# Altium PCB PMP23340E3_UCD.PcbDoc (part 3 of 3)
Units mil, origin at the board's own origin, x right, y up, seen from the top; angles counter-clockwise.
Board outline 2299.21 x 1157.48 mil, 14 copper layers (Top Layer, Layer 1, Layer 2, Layer 3, Layer 4, Layer 5, Layer 6, Layer 7, Layer 8, Layer 9, Layer 10, Layer 11, Layer 12, Bottom Layer), stack 130 mil thick; 242 components, 71 nets, 1021 pads, 321 vias.
Unrouted connection lines stored in the file: 1.
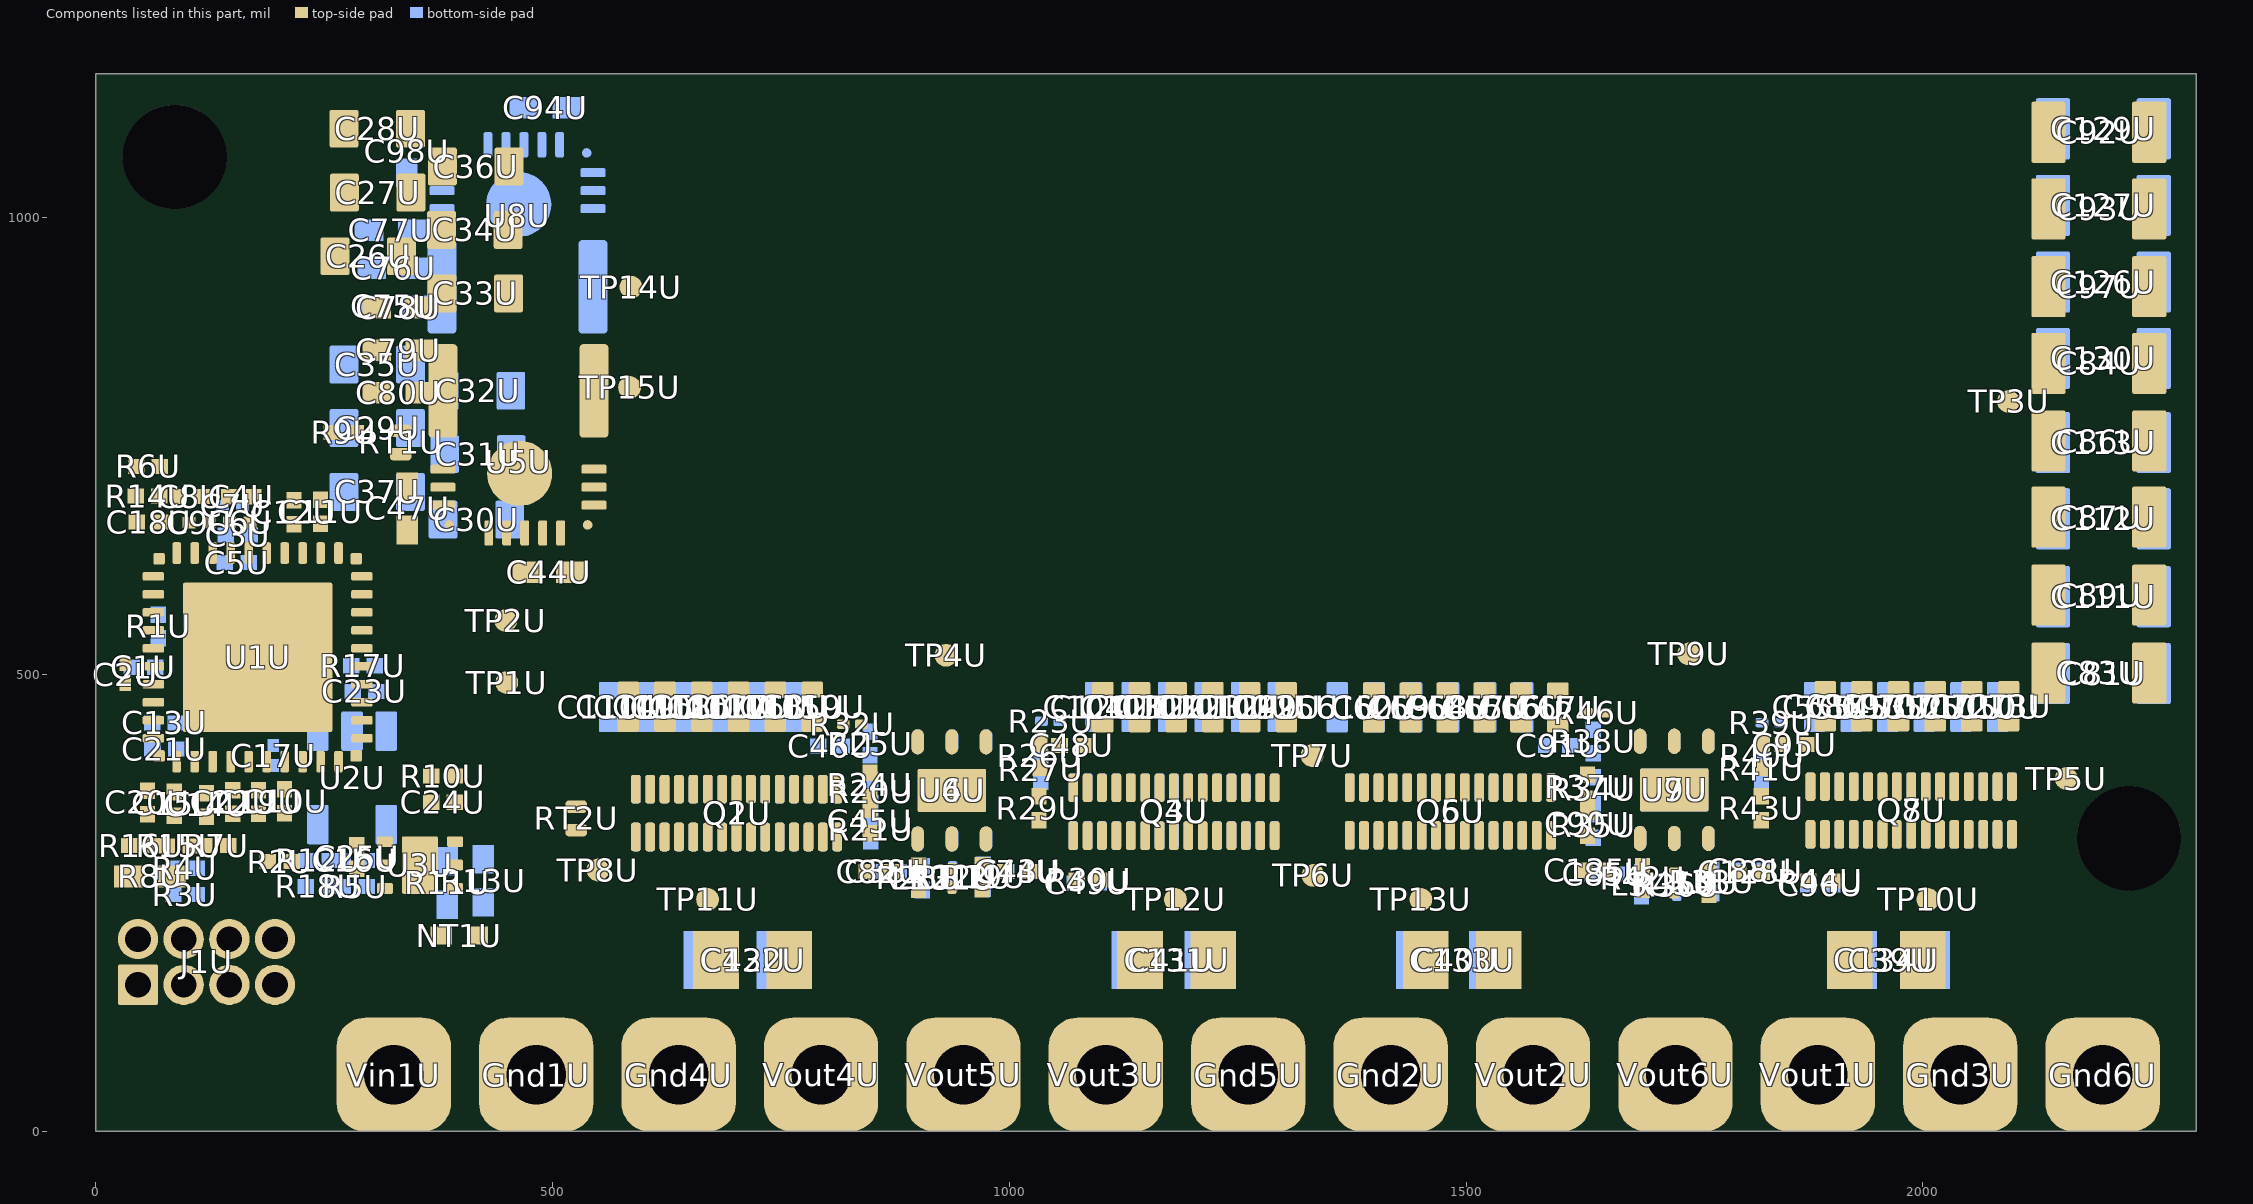
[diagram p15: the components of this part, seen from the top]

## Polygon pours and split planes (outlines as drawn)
3_3V_D on Layer 2 "LAYER_2_3_3V_D_P1355" (solid, pour order 1355): 18.43,785.67 307.08,785.67 307.08,641.01 307.08,240.65 17.11,240.65
Vsw2 on Layer 2 "LAYER_2_VSW2_P1378" (solid, remove dead copper, pour order 1378): 560.6,976.49 514.62,976.49 514.62,873.03 560.21,873.03
Vin on Layer 2 "LAYER_2_VIN_P1347" (solid, remove dead copper, pour order 1347): 258.75,-0.36 258.75,190.9 285.93,218.07 285.93,988.08 410.25,988.08 410.25,-0.36
Vsw2 on Layer 2 "LAYER_2_VSW2_P1360" (solid, pour order 1360): 1019,702.35 1102.45,702.35 1452.37,1052.26 1452.37,1157.48 1336.59,1157.48 1336.59,1041.7 1091.16,796.27 1019,796.27
Vsw2 on Layer 2 "LAYER_2_VSW2_P1359" (solid, pour order 1359): 1623.34,913.48 1544.79,913.48 1224.94,593.63 1224.94,464.14 1337.82,464.14 1337.82,615.42 1537.09,814.69 1623.34,814.69
Vsw2 on Layer 2 "LAYER_2_VSW2_P1358" (solid, pour order 1358): 825.77,813.5 825.77,772.44 745.11,772.44 587.65,929.9 587.65,1146.8 1327.7,1146.8 1327.7,1036.14 1105.05,813.5
Vsw2 on Layer 2 "LAYER_2_VSW2_P1357" (solid, pour order 1357): 1348.12,464.14 1348.12,609.51 1540.36,801.74 2184.87,801.74 2184.87,1132.49 2318.9,1132.49 2318.9,464.14
Vsw1 on Layer 2 "LAYER_2_VSW1_P1356" (solid, pour order 1356): 516.37,887.47 614.07,887.47 688.83,812.72 737.92,763.62 840.05,763.62 887.62,701.45 1109.66,701.45 1462.51,1054.3 1462.51,1157.48 2204.77,1157.48 2204.77,1103.27 2204.77,1054.3 2204.77,1012.9 2204.77,964.9 2204.77,929.81 2204.77,881.3 2204.77,843.85 2204.77,812.72 1762.75,812.72 1762.75,913.66 1531.32,913.66 1213.12,598 1213.12,464.73 516.37,464.73
GND on Layer 2 "LAYER_2_GND_P1337" (solid, remove dead copper, pour order 1337): 406.75,999.52 287.75,999.52 287.75,801.68 200.84,801.68 200.84,1142.83 516.38,1142.83 516.38,457.97 2299.21,457.97 2299.21,0 406.75,0
GND on Layer 1 "LAYER_1_GND_P1257" (solid, remove dead copper, pour order 1257): 409.05,393.09 409.05,651.79 267.66,793.18 20.22,793.18 20.22,1157.48 813.4,1157.48 813.4,0 409.05,0
AGND on Layer 1 "LAYER_1_AGND_P1366" (solid, remove dead copper, pour order 1366): -2.08,774.32 271.03,774.32 401.15,644.2 401.15,180.82 -0.49,183.79
Vin on Layer 1 "LAYER_1_VIN_P1409" (solid, remove dead copper, pour order 1409): 396.59,978.3 350.61,978.3 350.61,874.85 396.19,874.85
Vin on Layer 1 "LAYER_1_VIN_P1408" (solid, remove dead copper, pour order 1408): 396.58,862.96 350.61,862.96 350.61,758.81 396.58,758.81
Vsw2 on Layer 1 "LAYER_1_VSW2_P1388" (solid, remove dead copper, pour order 1388): 560.6,976.49 514.62,976.49 514.62,873.03 560.21,873.03
Vsw1 on Layer 1 "LAYER_1_VSW1_P1387" (solid, remove dead copper, pour order 1387): 560.6,861.14 514.62,861.14 514.62,757 560.6,757
Vout on Layer 1 "LAYER_1_VOUT_P1253" (solid, pour order 1253): 556.45,1159.56 1332.47,1159.56 1332.47,312.76 1055.48,312.76 1055.48,783.06 1048.79,783.06 1048.79,225.84 1169.05,105.58 1169.05,24.53 732.85,24.53 732.85,118.18 819.58,204.9 819.58,469.4 556.45,469.4
Vout on Layer 1 "LAYER_1_VOUT_P1254" (solid, pour order 1254): 2126.38,1159.56 1343.19,1159.56 1343.19,312.76 1627.35,312.76 1627.35,783.06 1634.04,783.06 1634.04,225.84 1513.78,105.58 1513.78,24.53 1949.98,24.53 1949.98,118.18 1863.25,204.9 1863.25,469.4 2126.38,469.4
GND on Layer 1 "LAYER_1_GND_P1259" (solid, remove dead copper, pour order 1259): 1042.74,446.09 1623.19,446.09 1623.19,0 1042.74,0
GND on Layer 1 "LAYER_1_GND_P1258" (solid, remove dead copper, pour order 1258): 1780.53,458.19 2299.21,458.19 2299.21,0 1780.53,0
Vsw2 on Layer 1 "LAYER_1_VSW2_P1256" (solid, remove dead copper, pour order 1256): 2180.71,1134.88 2299.21,1134.88 2299.21,468.21 2180.71,471.21
Vsw1 on Layer 1 "LAYER_1_VSW1_P1255" (solid, remove dead copper, pour order 1255): 2117.33,1129.97 2200.92,1129.97 2200.92,464.18 2117.33,466.29
Vsw1 on Layer 5 "LAYER_5_VSW1_P1385" (solid, remove dead copper, pour order 1385): 560.6,861.14 514.62,861.14 514.62,757 560.6,757
Vsw2 on Layer 5 "LAYER_5_VSW2_P1364" (solid, pour order 1364): 1636.57,713.56 1544.04,713.56 1238.17,1019.43 1238.17,1135.02 1350.46,1135.02 1350.46,1012.21 1562.32,800.35 1636.57,800.35
Vsw2 on Layer 5 "LAYER_5_VSW2_P1363" (solid, pour order 1363): 1054.5,897.77 1120.23,897.77 1439.92,578.08 1439.92,463.99 1327.98,463.99 1327.98,583.24 1101.83,809.38 1054.5,809.38
Vsw2 on Layer 5 "LAYER_5_VSW2_P1362" (solid, pour order 1362): 774.15,972.53 901.93,972.53 968.13,906.34 1126.73,906.34 1448.64,584.42 1448.64,463.61 2153.57,463.61 2153.57,1157.48 1359.29,1157.48 1359.29,1019.99 1564.59,814.69 1754.33,814.69 1754.33,703.2 1543.45,703.2 1230.33,1016.32 1230.33,1157.48 513.74,1157.48 513.74,878.54 680.16,878.54
Vsw2 on Layer 5 "LAYER_5_VSW2_P1361" (solid, pour order 1361): 775.5,960.07 901.14,960.07 ccw(c909.35,963.8) 902.97,957.43 1061.31,799.08 1108.02,799.08 1318.92,588.19 1318.92,464.37 558.32,464.37 558.32,875.88 691.31,875.88
Vin on Layer 5 "LAYER_5_VIN_P1352" (solid, remove dead copper, pour order 1352): 258.75,-0.36 258.75,190.9 285.93,218.07 285.93,976.65 410.25,976.65 410.25,-0.36
GND on Layer 5 "LAYER_5_GND_P1338" (solid, remove dead copper, pour order 1338): 414.88,980.66 284.75,980.66 284.75,799.39 234,799.39 234,1157.48 514.84,1157.48 514.84,745.48 553.1,745.48 553.1,452.31 2299.21,452.31 2299.21,0 414.88,0
Vsw2 on Layer 5 "LAYER_5_VSW2_P1282" (solid, remove dead copper, pour order 1282): 2180.71,1134.88 2299.21,1134.88 2299.21,468.21 2180.71,471.21
Vsw1 on Layer 5 "LAYER_5_VSW1_P1279" (solid, remove dead copper, pour order 1279): 2117.33,1129.97 2200.92,1129.97 2200.92,464.18 2117.33,466.29
Vsw2 on Layer 8 "LAYER_8_VSW2_P1386" (solid, remove dead copper, pour order 1386): 560.6,976.49 514.62,976.49 514.62,873.03 560.21,873.03
Vsw2 on Layer 8 "LAYER_8_VSW2_P1270" (solid, pour order 1270): 825.77,813.5 825.77,772.44 745.11,772.44 587.65,929.9 587.65,1146.8 1327.7,1146.8 1327.7,1036.14 1105.05,813.5
Vsw2 on Layer 8 "LAYER_8_VSW2_P1269" (solid, pour order 1269): 1348.12,464.14 1348.12,609.51 1540.36,801.74 2184.87,801.74 2184.87,1132.49 2318.9,1132.49 2318.9,464.14
Vsw2 on Layer 8 "LAYER_8_VSW2_P1271" (solid, pour order 1271): 1623.34,913.48 1544.79,913.48 1224.94,593.63 1224.94,464.14 1337.82,464.14 1337.82,615.42 1537.09,814.69 1623.34,814.69
Vsw1 on Layer 8 "LAYER_8_VSW1_P1268" (solid, pour order 1268): 516.37,887.47 614.07,887.47 688.83,812.72 737.92,763.62 840.05,763.62 887.62,701.45 1109.66,701.45 1462.51,1054.3 1462.51,1157.48 2204.77,1157.48 2204.77,1103.27 2204.77,1054.3 2204.77,1012.9 2204.77,964.9 2204.77,929.81 2204.77,881.3 2204.77,843.85 2204.77,812.72 1762.75,812.72 1762.75,913.66 1531.32,913.66 1213.12,598 1213.12,464.73 516.37,464.73
Vsw2 on Layer 8 "LAYER_8_VSW2_P1272" (solid, pour order 1272): 1019,702.35 1102.45,702.35 1452.37,1052.26 1452.37,1157.48 1336.59,1157.48 1336.59,1041.7 1091.16,796.27 1019,796.27
GND on Layer 8 "LAYER_8_GND_P1293" (solid, remove dead copper, pour order 1293): 405.41,647.24 253.13,744.64 253.13,1157.48 512.5,1157.48 512.5,453.78 2299.21,453.78 2299.21,0 405.41,0
Vsw2 on Top Layer "TOP_LAYER_VSW2_P1384" (solid, remove dead copper, pour order 1384): 560.6,976.49 514.62,976.49 514.62,873.03 560.21,873.03
Vsw1 on Top Layer "TOP_LAYER_VSW1_P1383" (solid, remove dead copper, pour order 1383): 560.6,861.14 514.62,861.14 514.62,757 560.6,757
AGND on Top Layer "TOP_LAYER_AGND_P1275" (solid, remove dead copper, pour order 1275): 266.64,302.42 266.64,188.92 377.87,188.92 377.87,372.47 332.48,372.47 332.48,302.42 266.82,302.57
AGND on Top Layer "TOP_LAYER_AGND_P1292" (solid, remove dead copper, pour order 1292): 48.39,303.15 48.39,358.77 217.26,358.77 217.26,331.76 105.07,331.76 89.73,316.42 89.73,303.15
GND on Top Layer "TOP_LAYER_GND_P1291" (solid, remove dead copper, pour order 1291): 327.66,1129.9 327.66,872.01 327.66,792.25 201.19,792.25 201.19,1129.9
3_3V_D on Top Layer "TOP_LAYER_3_3V_D_P1276" (solid, remove dead copper, pour order 1276): 276.99,371.06 325.14,419.2 413.74,419.2 413.74,383.76 413.74,337.84 389.58,313.68 371.86,313.68 371.86,308.84 366.22,303.21 361.38,308.04 276.09,308.04
AGND on Top Layer "TOP_LAYER_AGND_P1289" (solid, remove dead copper, pour order 1289): 56.78,707.06 56.78,635.02 72.09,619.71 114.26,619.71 114.26,671.67 102.71,683.22 102.71,707.06
AGND on Top Layer "TOP_LAYER_AGND_P1288" (solid, remove dead copper, pour order 1288): 160.94,649.89 160.94,737.96 274.23,737.96 317.12,695.06 317.12,580.96 273.8,580.96 273.8,649.22
GND on Top Layer "TOP_LAYER_GND_P1286" (solid, remove dead copper, pour order 1286): 420.62,1076.69 520.04,1076.69 520.04,680.23 420.62,680.23
Vin on Top Layer "TOP_LAYER_VIN_P1285" (solid, remove dead copper, pour order 1285): 331.09,1134.47 419.78,1134.47 419.78,737.89 359.66,737.89 359.66,800.51 331.09,800.51
GND on Top Layer "TOP_LAYER_GND_P1280" (solid, remove dead copper, pour order 1280): 416.39,455.12 2299.21,455.12 2299.21,0 416.39,0
Vout on Top Layer "TOP_LAYER_VOUT_P1283" (solid, pour order 1283): 560.55,1147.1 922.24,1147.1 922.24,936.49 935.03,936.49 935.03,1147.1 1332.5,1147.1 1332.5,464.44 560.55,464.44
Vout on Top Layer "TOP_LAYER_VOUT_P1281" (solid, pour order 1281): 1343.19,1157.48 1722.4,1157.48 1722.4,923.28 1736.57,923.28 1736.57,1157.48 2131.72,1157.48 2131.72,464.86 1343.19,464.86
Vsw2 on Top Layer "TOP_LAYER_VSW2_P1278" (solid, remove dead copper, pour order 1278): 2180.71,1134.88 2299.21,1134.88 2299.21,468.21 2180.71,471.21
Vsw1 on Top Layer "TOP_LAYER_VSW1_P1277" (solid, remove dead copper, pour order 1277): 2117.33,1129.97 2200.92,1129.97 2200.92,464.18 2117.33,466.29
Vsw2 on Layer 7 "LAYER_7_VSW2_P1400" (solid, remove dead copper, pour order 1400): 560.6,976.49 514.62,976.49 514.62,873.03 560.21,873.03
Vsw1 on Layer 7 "LAYER_7_VSW1_P1399" (solid, remove dead copper, pour order 1399): 560.6,861.14 514.62,861.14 514.62,757 560.6,757
AGND on Layer 7 "LAYER_7_AGND_P1365" (solid, remove dead copper, pour order 1365): 17.53,778.15 302.54,778.15 302.54,245.07 20.5,245.07
Vout on Layer 7 "LAYER_7_VOUT_P1252" (solid, pour order 1252): 556.45,1159.56 1332.47,1159.56 1332.47,312.76 1055.48,312.76 1055.48,783.06 1048.79,783.06 1048.79,225.84 1169.05,105.58 1169.05,24.53 732.85,24.53 732.85,118.18 819.58,204.9 819.58,469.4 556.45,469.4
Vout on Layer 7 "LAYER_7_VOUT_P1251" (solid, pour order 1251): 2126.38,1159.56 1343.19,1159.56 1343.19,312.76 1627.35,312.76 1627.35,783.06 1634.04,783.06 1634.04,225.84 1513.78,105.58 1513.78,24.53 1949.98,24.53 1949.98,118.18 1863.25,204.9 1863.25,469.4 2126.38,469.4
Vin on Layer 7 "LAYER_7_VIN_P1350" (solid, remove dead copper, pour order 1350): 258.75,-0.36 258.75,190.9 285.93,218.07 285.93,978 410.25,978 410.25,-0.36
GND on Layer 7 "LAYER_7_GND_P1332" (solid, remove dead copper, pour order 1332): 1780.53,459.66 2299.21,459.66 2299.21,-16.75 1780.53,-16.75
GND on Layer 7 "LAYER_7_GND_P1334" (solid, remove dead copper, pour order 1334): 415.67,983.29 283.8,983.29 283.8,790.61 181.57,790.61 181.57,1157.48 548.44,1157.48 548.44,464.07 860.05,464.07 860.05,0 415.67,0
GND on Layer 7 "LAYER_7_GND_P1336" (solid, remove dead copper, pour order 1336): 1042.74,446.09 1623.19,446.09 1623.19,0 1042.74,0
Vsw2 on Layer 7 "LAYER_7_VSW2_P1329" (solid, remove dead copper, pour order 1329): 2180.71,1134.88 2299.21,1134.88 2299.21,468.21 2180.71,471.21
Vsw1 on Layer 7 "LAYER_7_VSW1_P1327" (solid, remove dead copper, pour order 1327): 2117.33,1129.97 2200.92,1129.97 2200.92,464.18 2117.33,466.29
AGND on Bottom Layer "BOTTOM_LAYER_AGND_P1369" (solid, remove dead copper, pour order 1369): 155.55,715.2 153.5,713.16 153.5,613.67 151.46,613.67 79.81,542.02 79.81,521.14 56.47,521.14 50.74,515.41 50.74,479.79 74.9,455.64 74.9,400.78 290.65,400.78 306.21,416.34 291.06,431.48 291.06,717.25
3_3V_D on Bottom Layer "BOTTOM_LAYER_3_3V_D_P1370" (solid, remove dead copper, pour order 1370): 50.74,741.34 50.74,554.87 55.55,550.06 87.3,550.06 153.69,616.44 153.69,741.34
Vin on Bottom Layer "BOTTOM_LAYER_VIN_P1344" (solid, remove dead copper, pour order 1344): 312.98,1011.36 419.78,1011.36 419.78,642.84 312.98,642.84
GND on Bottom Layer "BOTTOM_LAYER_GND_P1345" (solid, remove dead copper, pour order 1345): 420.62,1075.89 520.04,1075.89 520.04,644.25 420.62,644.25
GND on Bottom Layer "BOTTOM_LAYER_GND_P1368" (solid, remove dead copper, pour order 1368): 327.31,1129.9 327.31,872.01 314.28,872.01 287.68,845.42 287.68,682.74 200.84,682.74 200.84,1129.9
Vsw1 on Bottom Layer "BOTTOM_LAYER_VSW1_P1391" (solid, remove dead copper, pour order 1391): 560.6,861.14 514.62,861.14 514.62,757 560.6,757
Vsw2 on Bottom Layer "BOTTOM_LAYER_VSW2_P1396" (solid, remove dead copper, pour order 1396): 560.6,976.49 514.62,976.49 514.62,873.03 560.21,873.03
3_3V_D on Bottom Layer "BOTTOM_LAYER_3_3V_D_P1367" (solid, remove dead copper, pour order 1367): 180.45,407.08 255.36,407.08 255.36,310.82 249.95,305.41 211.06,305.41 203.62,297.96 202.79,298.79 180.45,298.79
Vout on Bottom Layer "BOTTOM_LAYER_VOUT_P1274" (solid, pour order 1274): 547.21,1155.96 922.22,1155.96 922.22,945.35 935.6,945.35 935.6,1155.96 1332.23,1155.96 1332.23,464.44 547.21,464.44
Vout on Bottom Layer "BOTTOM_LAYER_VOUT_P1273" (solid, pour order 1273): 1343.08,1157.48 1722.4,1157.48 1722.4,923.28 1736.57,923.28 1736.57,1157.48 2131.72,1157.48 2131.72,464.75 1343.08,464.75
GND on Bottom Layer "BOTTOM_LAYER_GND_P1315" (solid, remove dead copper, pour order 1315): 435.08,457.01 2299.21,457.01 2299.21,0 435.08,0
Vsw2 on Bottom Layer "BOTTOM_LAYER_VSW2_P1261" (solid, remove dead copper, pour order 1261): 2180.71,1134.88 2299.21,1134.88 2299.21,468.21 2180.71,471.21
Vsw1 on Bottom Layer "BOTTOM_LAYER_VSW1_P1260" (solid, remove dead copper, pour order 1260): 2117.33,1129.97 2200.92,1129.97 2200.92,464.18 2117.33,466.29
Vsw1 on Layer 11 "LAYER_11_VSW1_P1404" (solid, remove dead copper, pour order 1404): 560.6,861.14 514.62,861.14 514.62,757 560.6,757
5V on Layer 11 "LAYER_11_5V_P1376" (solid, remove dead copper, pour order 1376): 253.54,247.07 259.22,252.75 304.95,252.75 333.37,224.33 424.06,224.33 450.86,197.53 1646.94,197.53 1664.81,215.4 1680.23,215.4 1680.23,152.06 253.54,152.06
Vsw2 on Layer 11 "LAYER_11_VSW2_P1265" (solid, pour order 1265): 774.15,972.53 901.93,972.53 968.13,906.34 1126.73,906.34 1448.64,584.42 1448.64,463.61 2153.57,463.61 2153.57,1157.48 1359.29,1157.48 1359.29,1019.99 1564.59,814.69 1754.33,814.69 1754.33,703.2 1543.45,703.2 1230.33,1016.32 1230.33,1157.48 513.74,1157.48 513.74,878.54 680.16,878.54
Vsw2 on Layer 11 "LAYER_11_VSW2_P1264" (solid, pour order 1264): 775.5,960.07 901.14,960.07 ccw(c909.35,963.8) 902.97,957.43 1061.31,799.08 1108.02,799.08 1318.92,588.19 1318.92,464.37 558.32,464.37 558.32,875.88 691.31,875.88
Vsw2 on Layer 11 "LAYER_11_VSW2_P1266" (solid, pour order 1266): 1054.5,897.77 1120.23,897.77 1439.92,578.08 1439.92,463.99 1327.98,463.99 1327.98,583.24 1101.83,809.38 1054.5,809.38
Vsw2 on Layer 11 "LAYER_11_VSW2_P1267" (solid, pour order 1267): 1636.57,713.56 1544.04,713.56 1238.17,1019.43 1238.17,1135.02 1350.46,1135.02 1350.46,1012.21 1562.32,800.35 1636.57,800.35
Vin on Layer 11 "LAYER_11_VIN_P1348" (solid, remove dead copper, pour order 1348): 258.75,-0.36 258.75,136.24 410.25,136.24 410.25,-0.36
GND on Layer 11 "LAYER_11_GND_P1314" (solid, remove dead copper, pour order 1314): 410.39,636.73 249.05,762.9 249.05,1157.48 518.77,1157.48 518.77,455.25 2299.21,455.25 2299.21,0 410.39,0
Vsw2 on Layer 11 "LAYER_11_VSW2_P1263" (solid, remove dead copper, pour order 1263): 2180.71,1134.88 2299.21,1134.88 2299.21,468.21 2180.71,471.21
Vsw1 on Layer 11 "LAYER_11_VSW1_P1262" (solid, remove dead copper, pour order 1262): 2117.33,1129.97 2200.92,1129.97 2200.92,464.18 2117.33,466.29
Vsw1 on Layer 6 "LAYER_6_VSW1_P1395" (solid, remove dead copper, pour order 1395): 560.6,861.14 514.62,861.14 514.62,757 560.6,757
Vsw2 on Layer 6 "LAYER_6_VSW2_P1394" (solid, remove dead copper, pour order 1394): 560.6,976.49 514.62,976.49 514.62,873.03 560.21,873.03
Vin on Layer 6 "LAYER_6_VIN_P1351" (solid, remove dead copper, pour order 1351): 258.75,-0.36 258.75,190.9 277.34,209.48 277.34,973.81 410.25,973.81 410.25,-0.36
Vout on Layer 6 "LAYER_6_VOUT_P1249" (solid, pour order 1249): 556.45,1159.56 1332.47,1159.56 1332.47,312.76 1055.48,312.76 1055.48,783.06 1048.79,783.06 1048.79,225.84 1169.05,105.58 1169.05,24.53 732.85,24.53 732.85,118.18 819.58,204.9 819.58,469.4 556.45,469.4
Vout on Layer 6 "LAYER_6_VOUT_P1250" (solid, pour order 1250): 2126.38,1159.56 1343.19,1159.56 1343.19,312.76 1627.35,312.76 1627.35,783.06 1634.04,783.06 1634.04,225.84 1513.78,105.58 1513.78,24.53 1949.98,24.53 1949.98,118.18 1863.25,204.9 1863.25,469.4 2126.38,469.4
GND on Layer 6 "LAYER_6_GND_P1311" (solid, remove dead copper, pour order 1311): 405.63,990.63 288.68,990.63 288.68,800.38 215.38,800.38 215.38,1157.48 549.82,1157.48 549.82,456.72 860.05,456.72 860.05,0 414.1,0
GND on Layer 6 "LAYER_6_GND_P1305" (solid, remove dead copper, pour order 1305): 1042.74,446.09 1623.19,446.09 1623.19,0 1042.74,0
GND on Layer 6 "LAYER_6_GND_P1308" (solid, remove dead copper, pour order 1308): 1780.53,458.19 2299.21,458.19 2299.21,0 1780.53,0
Vsw2 on Layer 6 "LAYER_6_VSW2_P1299" (solid, remove dead copper, pour order 1299): 2180.71,1134.88 2299.21,1134.88 2299.21,468.21 2180.71,471.21
Vsw1 on Layer 6 "LAYER_6_VSW1_P1296" (solid, remove dead copper, pour order 1296): 2117.33,1129.97 2200.92,1129.97 2200.92,464.18 2117.33,466.29
Vin on Layer 12 "LAYER_12_VIN_P1415" (solid, remove dead copper, pour order 1415): 397.8,978.3 351.82,978.3 351.82,874.85 397.4,874.85
Vin on Layer 12 "LAYER_12_VIN_P1414" (solid, remove dead copper, pour order 1414): 397.79,862.96 351.82,862.96 351.82,758.81 397.79,758.81
Vsw2 on Layer 12 "LAYER_12_VSW2_P1407" (solid, remove dead copper, pour order 1407): 560.6,976.49 514.62,976.49 514.62,873.03 560.21,873.03
Vsw1 on Layer 12 "LAYER_12_VSW1_P1406" (solid, remove dead copper, pour order 1406): 560.6,861.14 514.62,861.14 514.62,757 560.6,757
AGND on Layer 12 "LAYER_12_AGND_P1375" (solid, remove dead copper, pour order 1375): 15.75,780.06 213.04,780.06 407.59,585.51 407.59,240.59 14.13,240.59
Vin on Layer 12 "LAYER_12_VIN_P1373" (solid, remove dead copper, pour order 1373): 258.75,-0.36 258.75,190.9 285.93,218.07 410.25,218.07 410.25,-0.36
Vout on Layer 12 "LAYER_12_VOUT_P1284" (solid, pour order 1284): 556.45,1159.56 1332.47,1159.56 1332.47,312.76 1055.48,312.76 1055.48,783.06 1048.79,783.06 1048.79,225.84 1169.05,105.58 1169.05,24.53 732.85,24.53 732.85,118.18 819.58,204.9 819.58,469.4 556.45,469.4
Vout on Layer 12 "LAYER_12_VOUT_P1287" (solid, pour order 1287): 2126.38,1159.56 1343.19,1159.56 1343.19,312.76 1627.35,312.76 1627.35,783.06 1634.04,783.06 1634.04,225.84 1513.78,105.58 1513.78,24.53 1949.98,24.53 1949.98,118.18 1863.25,204.9 1863.25,469.4 2126.38,469.4
GND on Layer 12 "LAYER_12_GND_P1297" (solid, remove dead copper, pour order 1297): 418.02,587.77 216.5,789.29 216.5,1157.48 860.05,1157.48 860.05,0 418.02,0
GND on Layer 12 "LAYER_12_GND_P1295" (solid, remove dead copper, pour order 1295): 1780.53,459.66 2299.21,459.66 2299.21,0 1780.53,0
GND on Layer 12 "LAYER_12_GND_P1298" (solid, remove dead copper, pour order 1298): 1042.74,446.09 1623.19,446.09 1623.19,0 1042.74,0
Vsw2 on Layer 12 "LAYER_12_VSW2_P1294" (solid, remove dead copper, pour order 1294): 2180.71,1134.88 2299.21,1134.88 2299.21,468.21 2180.71,471.21
Vsw1 on Layer 12 "LAYER_12_VSW1_P1290" (solid, remove dead copper, pour order 1290): 2117.33,1129.97 2200.92,1129.97 2200.92,464.18 2117.33,466.29
Vin on Layer 3 "LAYER_3_VIN_P1411" (solid, remove dead copper, pour order 1411): 395.98,975.88 350,975.88 350,872.43 395.59,872.43
Vin on Layer 3 "LAYER_3_VIN_P1410" (solid, remove dead copper, pour order 1410): 395.98,860.54 350,860.54 350,756.39 395.98,756.39
Vsw2 on Layer 3 "LAYER_3_VSW2_P1390" (solid, remove dead copper, pour order 1390): 560.6,976.49 514.62,976.49 514.62,873.03 560.21,873.03
Vsw1 on Layer 3 "LAYER_3_VSW1_P1389" (solid, remove dead copper, pour order 1389): 560.6,861.14 514.62,861.14 514.62,757 560.6,757
5V on Layer 3 "LAYER_3_5V_P1353" (solid, remove dead copper, pour order 1353): -3.11,1157.48 529.65,1157.48 529.65,1073.96 359.18,903.49 359.18,850.25 499.23,710.2 499.23,181.47 -0.49,181.47
Vout on Layer 3 "LAYER_3_VOUT_P1302" (solid, pour order 1302): 558.5,1159.53 1332.44,1159.53 1332.44,454.4 1049.09,454.4 1049.09,224.71 1168.99,104.81 1168.99,9.23 731.6,9.23 731.6,117.67 818.84,204.91 818.84,777.75 811.36,777.75 811.36,309.44 558.5,309.44
Vout on Layer 3 "LAYER_3_VOUT_P1300" (solid, pour order 1300): 2117.22,1159.92 1343.28,1159.92 1343.28,454.79 1626.63,454.79 1626.63,225.1 1506.74,105.2 1506.74,9.62 1944.12,9.62 1944.12,118.06 1856.88,205.3 1856.88,778.14 1864.36,778.14 1864.36,309.83 2117.22,309.83
Vin on Layer 3 "LAYER_3_VIN_P1346" (solid, remove dead copper, pour order 1346): 258.75,-0.36 258.75,190.9 285.93,218.07 285.93,310.54 410.25,310.54 410.25,-0.36
GND on Layer 3 "LAYER_3_GND_P1342" (solid, remove dead copper, pour order 1342): 1780.53,452.31 2299.21,452.31 2299.21,0 1780.53,0
GND on Layer 3 "LAYER_3_GND_P1341" (solid, remove dead copper, pour order 1341): 407.4,310.26 860.05,310.26 860.05,0 407.4,0
GND on Layer 3 "LAYER_3_GND_P1343" (solid, remove dead copper, pour order 1343): 1042.74,446.09 1623.19,446.09 1623.19,-16.41 1042.74,-16.41
Vsw2 on Layer 3 "LAYER_3_VSW2_P1340" (solid, remove dead copper, pour order 1340): 2180.71,1134.88 2299.21,1134.88 2299.21,468.21 2180.71,471.21
Vsw1 on Layer 3 "LAYER_3_VSW1_P1339" (solid, remove dead copper, pour order 1339): 2117.33,1129.97 2200.92,1129.97 2200.92,464.18 2117.33,466.29
Vin on Layer 4 "LAYER_4_VIN_P1413" (solid, remove dead copper, pour order 1413): 395.98,861.14 350,861.14 350,757 395.98,757
Vin on Layer 4 "LAYER_4_VIN_P1412" (solid, remove dead copper, pour order 1412): 395.98,976.49 350,976.49 350,873.03 395.59,873.03
Vsw1 on Layer 4 "LAYER_4_VSW1_P1393" (solid, remove dead copper, pour order 1393): 560.6,861.14 514.62,861.14 514.62,757 560.6,757
Vsw2 on Layer 4 "LAYER_4_VSW2_P1392" (solid, remove dead copper, pour order 1392): 560.6,976.49 514.62,976.49 514.62,873.03 560.21,873.03
GND on Layer 4 "LAYER_4_GND_P1312" (solid, remove dead copper, pour order 1312): 407.11,1152.79 819.73,1148.03 819.73,0 407.11,0
Vout on Layer 4 "LAYER_4_VOUT_P1303" (solid, pour order 1303): 558.5,1159.53 1332.44,1159.53 1332.44,454.4 1049.09,454.4 1049.09,224.71 1168.99,104.81 1168.99,9.23 731.6,9.23 731.6,117.67 818.84,204.91 818.84,777.75 811.36,777.75 811.36,309.44 558.5,309.44
Vout on Layer 4 "LAYER_4_VOUT_P1304" (solid, pour order 1304): 2117.22,1159.92 1343.28,1159.92 1343.28,454.79 1626.63,454.79 1626.63,225.1 1506.74,105.2 1506.74,9.62 1944.12,9.62 1944.12,118.06 1856.88,205.3 1856.88,778.14 1864.36,778.14 1864.36,309.83 2117.22,309.83
Vin on Layer 4 "LAYER_4_VIN_P1313" (solid, remove dead copper, pour order 1313): 258.75,-0.36 258.75,190.9 285.93,218.07 285.93,293.57 410.25,293.57 410.25,-0.36
GND on Layer 4 "LAYER_4_GND_P1309" (solid, remove dead copper, pour order 1309): 1780.53,455.25 2299.21,455.25 2299.21,0 1780.53,0
GND on Layer 4 "LAYER_4_GND_P1310" (solid, remove dead copper, pour order 1310): 1042.74,446.09 1623.19,446.09 1623.19,0 1042.74,0
Vsw2 on Layer 4 "LAYER_4_VSW2_P1307" (solid, remove dead copper, pour order 1307): 2180.71,1134.88 2299.21,1134.88 2299.21,468.21 2180.71,471.21
Vsw1 on Layer 4 "LAYER_4_VSW1_P1306" (solid, remove dead copper, pour order 1306): 2117.33,1129.97 2200.92,1129.97 2200.92,464.18 2117.33,466.29
Vsw2 on Layer 9 "LAYER_9_VSW2_P1402" (solid, remove dead copper, pour order 1402): 560.6,976.49 514.62,976.49 514.62,873.03 560.21,873.03
Vsw1 on Layer 9 "LAYER_9_VSW1_P1401" (solid, remove dead copper, pour order 1401): 560.6,861.14 514.62,861.14 514.62,757 560.6,757
Vout on Layer 9 "LAYER_9_VOUT_P1324" (solid, pour order 1324): 558.5,1159.53 1332.44,1159.53 1332.44,454.4 1049.09,454.4 1049.09,224.71 1168.99,104.81 1168.99,9.23 731.6,9.23 731.6,117.67 818.84,204.91 818.84,777.75 811.36,777.75 811.36,309.44 558.5,309.44
Vout on Layer 9 "LAYER_9_VOUT_P1322" (solid, pour order 1322): 2117.22,1159.92 1343.28,1159.92 1343.28,454.79 1626.63,454.79 1626.63,225.1 1506.74,105.2 1506.74,9.62 1944.12,9.62 1944.12,118.06 1856.88,205.3 1856.88,778.14 1864.36,778.14 1864.36,309.83 2117.22,309.83
Vin on Layer 9 "LAYER_9_VIN_P1335" (solid, remove dead copper, pour order 1335): 258.75,-0.36 258.75,190.9 285.93,218.07 285.93,979.44 410.25,979.44 410.25,-0.36
GND on Layer 9 "LAYER_9_GND_P1333" (solid, remove dead copper, pour order 1333): 1780.53,459.66 2299.21,459.66 2299.21,0 1780.53,0
GND on Layer 9 "LAYER_9_GND_P1330" (solid, remove dead copper, pour order 1330): 413.32,985.92 285.16,985.92 285.16,784.3 216.19,784.3 216.19,1157.48 543.32,1157.48 543.32,316.31 860.05,316.31 860.05,0 413.32,0
GND on Layer 9 "LAYER_9_GND_P1331" (solid, remove dead copper, pour order 1331): 1042.74,446.09 1623.19,446.09 1623.19,0 1042.74,0
Vsw2 on Layer 9 "LAYER_9_VSW2_P1328" (solid, remove dead copper, pour order 1328): 2180.71,1134.88 2299.21,1134.88 2299.21,468.21 2180.71,471.21
Vsw1 on Layer 9 "LAYER_9_VSW1_P1326" (solid, remove dead copper, pour order 1326): 2117.33,1129.97 2200.92,1129.97 2200.92,464.18 2117.33,466.29
Vsw2 on Layer 10 "LAYER_10_VSW2_P1405" (solid, remove dead copper, pour order 1405): 560.6,976.49 514.62,976.49 514.62,873.03 560.21,873.03
Vsw1 on Layer 10 "LAYER_10_VSW1_P1403" (solid, remove dead copper, pour order 1403): 560.6,861.14 514.62,861.14 514.62,757 560.6,757
Vout on Layer 10 "LAYER_10_VOUT_P1316" (solid, pour order 1316): 558.5,1159.53 1332.44,1159.53 1332.44,454.4 1049.09,454.4 1049.09,224.71 1168.99,104.81 1168.99,9.23 731.6,9.23 731.6,117.67 818.84,204.91 818.84,777.75 811.36,777.75 811.36,309.44 558.5,309.44
Vout on Layer 10 "LAYER_10_VOUT_P1317" (solid, pour order 1317): 2117.22,1159.92 1343.28,1159.92 1343.28,454.79 1626.63,454.79 1626.63,225.1 1506.74,105.2 1506.74,9.62 1944.12,9.62 1944.12,118.06 1856.88,205.3 1856.88,778.14 1864.36,778.14 1864.36,309.83 2117.22,309.83
Vin on Layer 10 "LAYER_10_VIN_P1325" (solid, remove dead copper, pour order 1325): 258.75,-0.36 258.75,190.9 285.93,218.07 285.93,979.55 410.25,979.55 410.25,-0.36
GND on Layer 10 "LAYER_10_GND_P1323" (solid, remove dead copper, pour order 1323): 1780.53,458.19 2299.21,458.19 2299.21,0 1780.53,0
GND on Layer 10 "LAYER_10_GND_P1320" (solid, remove dead copper, pour order 1320): 411.75,982.02 284.93,982.02 284.93,784.04 228.06,784.04 226.58,1157.48 547.37,1157.48 547.37,448.08 860.05,448.08 860.05,0 411.75,0
GND on Layer 10 "LAYER_10_GND_P1321" (solid, remove dead copper, pour order 1321): 1042.74,446.09 1623.19,446.09 1623.19,0 1042.74,0
Vsw2 on Layer 10 "LAYER_10_VSW2_P1319" (solid, remove dead copper, pour order 1319): 2180.71,1134.88 2299.21,1134.88 2299.21,468.21 2180.71,471.21
Vsw1 on Layer 10 "LAYER_10_VSW1_P1318" (solid, remove dead copper, pour order 1318): 2117.33,1129.97 2200.92,1129.97 2200.92,464.18 2117.33,466.29
GND on Top Solder "NONET_L-01_P-001" (solid): 1673.46,462.32 1710,462.32 1710,443.73 1673.46,443.73
GND on Top Solder "NONET_L-01_P-001" (solid): 880.29,461.92 916.83,461.92 916.83,443.33 880.29,443.33
GND on Bottom Solder "NONET_L-01_P-001" (solid): 956.4,464.95 992.94,464.95 992.94,446.36 956.4,446.36
GND on Bottom Solder "NONET_L-01_P-001" (solid): 1746.67,464.3 1783.21,464.3 1783.21,445.71 1746.67,445.71

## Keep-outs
Keep-Out Layer:
  text ".Layer_Name" at 577,-858.49 h60

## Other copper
Top Layer:
  text ".Layer_Name" at 577,-858.49 h60
Bottom Layer:
  text ".Layer_Name" at 577,-858.49 h60

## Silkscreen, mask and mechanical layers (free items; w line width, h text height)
Top Overlay:
  lines w10: 0,255.91 2299.21,255.91 ; 230.79,329.2 256.75,303.24 256.75,226.79 ; 252.42,160.44 447.15,160.44 447.15,229.68 252.42,229.68 252.42,160.44
  text "UCD" at 45.83,921.1 h30
  text "+" at 343.75,761.6 h30
  text "-" at 347.11,726.03 h30
  text "'.PRJ_Number'.PCB_Rev" at 2045.38,557.45 h75 r90
  text "+" at 517.4,363.14 h30
  text "-" at 516.73,297.27 h30
  text ".Layer_Name" at 577,-858.49 h60
Bottom Overlay:
  lines w10: 0,255.91 2299.21,255.91
  text ".Layer_Name" at 577,-858.49 h60
Top Paste:
  text ".Layer_Name" at 577,-858.49 h60
Bottom Paste:
  text ".Layer_Name" at 577,-858.49 h60
Top Solder:
  text ".Layer_Name" at 577,-858.49 h60
  text ".Layer_Name" at 577,-858.49 h60
Bottom Solder:
  text ".Layer_Name" at 577,-858.49 h60
Drill Guide:
  text ".Layer_Name" at 577,-858.49 h60
M1 Board Outline:
  circle w10: c1729.14,819.37 r145.67
  circle w10: c928.35,819.37 r145.67
  lines w10: 0,0 0,1157.48 2299.21,1157.48 2299.21,0 0,0
  text ".Layer_Name" at 577,-858.49 h60
M2 Board Dimensions:
  rectangle: 2875.2,-173.02 3250.2,-48.02
  rectangle: 0,-19.09 125,105.91
  lines w7: 0,-19.09 1000,-19.09 ; 2875.2,-173.02 2875.2,76.98 ; 3000.2,-173.02 3000.2,76.98 ; 3250.2,-173.02 3250.2,76.98 ; 3500.2,-173.02 3500.2,76.98 ; 2750.2,-173.02 2750.2,76.98 3750.2,76.98 3750.2,-173.02 2750.2,-173.02
  text ".Layer_Name" at 577,-858.49 h60
M3 3D STEP Top:
  text ".Layer_Name" at 577,-858.49 h60
M4 3D STEP Bottom:
  text ".Layer_Name" at 577,-858.49 h60
Top M5 Assembly Top/M6 Assembly Bottom:
  lines w10: -292,-930.17 6308,-930.17 ; -292,-726.83 6310,-726.83 ; -292,-523.5 -292,-1133.5 3713,-1133.5 6310,-1133.5 6310,-523.5 -291.5,-523.5 -291.5,-1133.5 1284,-1133.5 ; 2173,-1133.5 2173,-523.5 ; 3440,-726.83 3440,-523.5 ; 4280,-726.83 4280,-523.5 ; 4902,-1140 4902,-937.17
  text "COMPONENTS MARKED 'DNP' SHOULD NOT BE POPULATED." at 25.22,2748.85 h60
  text "ASSEMBLY VARIANT:" at 25.22,2636.47 h60
  text "RT1 & RT2 are polarized. Align with polarity shown in assembly drawing." at 7.64,1263.55 h60
  text "+" at 349.91,757.56 h30
  text "-" at 349.91,722.28 h30
  text "+" at 484.93,346.93 h30
  text "-" at 484.93,311.65 h30
  text ".VariantName" at 2613.3,-420.67 h60
  text "PCB VIEWED FROM TOP SIDE" at -228.5,-655.67 h60
  text "BOARD #:" at 2248,-655.67 h60
  text ".PRJ_Number" at 2793.5,-655.67 h60
  text "REV:" at 3638,-655.67 h60
  text ".PCB_Rev" at 3929.5,-655.67 h60
  text "SVN REV:" at 4476,-655.67 h60
  text ".VersionControl_RevNumber" at 4982,-655.67 h60
  text "PLOT NAME =" at -228.5,-1064.34 h60
  text ".plot_File_Name" at 577,-1064.34 h60
  text "GENERATED    :" at 2250,-1064.34 h60
  text ".Print_Date" at 3119.5,-1064.34 h60
  text ".Print_Time" at 3848.5,-1064.34 h60
  text "TEXAS INSTRUMENTS" at 5113,-1064.34 h60
Bottom M5 Assembly Top/M6 Assembly Bottom:
  lines w10: -292.5,-727.33 6309.5,-727.33 ; -290.5,-930.67 6309.5,-930.67 ; 1115.5,-1140.5 1115.5,-937.67 ; 1737.5,-727.33 1737.5,-524 ; 2577.5,-727.33 2577.5,-524 ; 3844.5,-1134 3844.5,-524 ; 4733.5,-1134 6309,-1134 6309,-524 -292.5,-524 -292.5,-1134 2304.5,-1134 6309.5,-1134 6309.5,-524
  text ".VariantName" at 5058,-434 h60
  text ".VersionControl_RevNumber" at 1035.5,-656.17 h60
  text "SVN REV:" at 1541.5,-656.17 h60
  text ".PCB_Rev" at 2088,-656.17 h60
  text "REV:" at 2379.5,-656.17 h60
  text ".PRJ_Number" at 3224,-656.17 h60
  text "BOARD #:" at 3769.5,-656.17 h60
  text "PCB VIEWED FROM BOTTOM SIDE" at 6246,-656.17 h60
  text "COMPONENTS MARKED 'DNP' SHOULD NOT BE POPULATED." at 9451.9,-767.17 h60
  text "ASSEMBLY VARIANT:" at 9451.9,-894.37 h60
  text "TEXAS INSTRUMENTS" at 904.5,-1064.84 h60
  text ".Print_Time" at 2169,-1064.84 h60
  text ".Print_Date" at 2898,-1064.84 h60
  text "GENERATED    :" at 3767.5,-1064.84 h60
  text ".plot_File_Name" at 5440.5,-1064.84 h60
  text "PLOT NAME =" at 6246,-1064.84 h60
M9 Title Sheet:
  drawing of 56 lines, arcs and shapes, not listed
  text "1" at 1058.34,13381.39 h70
  text "2" at 4384,13381.39 h70
  text "3" at 7714,13381.39 h70
  text "4" at 11049,13381.39 h70
  text "5" at 14374,13381.39 h70
  text "6" at 17709,13381.39 h70
  text "A" at -463,11603.39 h70
  text "A" at 19237,11603.39 h70
  text "B" at -463,7853.39 h70
  text "B" at 19237,7853.39 h70
  text "C" at -463,4103.39 h70
  text "C" at 19237,4103.39 h70
  text "D" at -463,353.39 h70
  text "D" at 19237,353.39 h70
  text "PROJECT TITLE:" at 16143,268.39 h45
  text ".PRJ_Title" at 16193,135.06 h70
  text "DESIGNED FOR:" at 16143,-32.61 h45
  text ".PRJ_Customer" at 16193,-172.61 h70
  text "FILE NAME:" at 16143,-332.61 h45
  text ".PCB_File_Name_No_Path" at 16193,-452.61 h70
  text "Texas Instruments (TI) and/or its licensors do not warrant the accuracy or completeness of this specification" at 11173.5,-614.45 h45
  text "ENGINEER:" at 16143,-622.61 h45
  text "LAYOUT BY:" at 17648,-622.61 h45
  text "or any information contained therein. TI and/or its licensors do not warrant that this design will meet" at 11128.51,-727.11 h45
  text ".PRJ_Engineer" at 16193,-777.6 h70
  text ".PCB_Layout" at 17698.5,-777.6 h70
  text "the specifications, will be suitable for your application or fit for any particular purpose, or will operate in" at 11128.51,-839.78 h45
  text ".Layer_Name" at 577,-858.49 h60
  text "ALTIUM DESIGNER VERSION:" at 17648,-932.61 h45
  text "an implementation. TI and/or its licensors do not warrant that the design is production worthy. You should" at 11128.51,-952.44 h45
  text "completely validate and test your design implementation to confirm the system functionality for your application." at 11173.5,-1065.11 h45
  text ".print_Scale" at 16193,-1065.94 h70
  text ".Application_BuildNumber" at 17698.5,-1065.94 h70
  text "1" at 1058.34,-1318.61 h70
  text "2" at 4384,-1318.61 h70
  text "3" at 7714,-1318.61 h70
  text "4" at 11049,-1318.61 h70
  text "5" at 14374,-1318.61 h70
  text "6" at 17709,-1318.61 h70
M10 Fab Notes:
  text "1. Any changes to the design must be approved by TI in writing. / 2. Fabricate using Gerber artwork. Do not add any text, logos, etc. to the top side of the board. / 3. Acceptability of PCB Fabrication, except as specified in this drawing, must comply to IPC-6012E, class 2. / Compelete array flatness must be within 7.5 mil per inch / 4. Material, Copper Clad Laminate sheet in accordance with IPC-4101. / Material: Use FR370-HR Substrate or similar. Must have the following Properties: / a. Tg(min) = 180 degrees C / b. Td(min) = 340 degrees C / c. Flame rating 94V0 / d. Dielectric = 4.0-5.0 / Layer to layer registration to be within 0.003 inches unless specified differently / 5. All holes to be located by pad centers / All PTH holes to be Copper (Cu) Plated thru per IPC-2221, 0.000787 inches min. thickness and be within .003 inches dia. / of true position / All NPTH hole be within .002 inches dia. of true position / 6. All vias (0.010 inches hole and smaller) to be covered with soldermask (tented) on both sides of the board per Gerber and / follow IPC4761 type VII via (filled (non conductive) and plated over). / 7. Solder mask created 1:1, do not enlarge or modify. / Do not clip solder mask. / Solder Mask over bare Copper, both sides, using Taiyu 4000HFX L.P.I or PSR-2000/ LF02/CA-25 or equiv., / Color green per IPC-SM-840, class T, RoHS Compliant / LDI mask must be used to register tolerance. / Solder Mask to copper layer registration to be within 0.003 inches / 8. Finish, all exposed Copper, both sides, after solder mask, to be Electroless Nickle Immersion Gold (Ni thickness / typical 150 micro inches and Au 3-5 micro inches) in accordance with IPC-45529. / 9. Silkscreen Both sides using white permanent ink. / Silkscreen to copper layer registration to be within 0.003 inches" at 6174.4,351.43 h60
  text ".Layer_Name" at 577,-858.49 h60
M11 Gerber Information:
  lines w10: -292,-930.17 6308,-930.17 ; -292,-726.83 6310,-726.83 ; -292,-523.5 -292,-1133.5 3713,-1133.5 6310,-1133.5 6310,-523.5 -291.5,-523.5 -291.5,-1133.5 1284,-1133.5 ; 2173,-1133.5 2173,-523.5 ; 3440,-726.83 3440,-523.5 ; 4280,-726.83 4280,-523.5 ; 4902,-1140 4902,-937.17
  text "ALL ARTWORK VIEWED FROM TOP SIDE" at -228.5,-655.67 h60
  text "BOARD #:" at 2248,-655.67 h60
  text ".PRJ_Number" at 2793.5,-655.67 h60
  text "REV:" at 3638,-655.67 h60
  text ".PCB_Rev" at 3929.5,-655.67 h60
  text "SVN REV:" at 4476,-655.67 h60
  text ".VersionControl_RevNumber" at 4982,-655.67 h60
  text "LAYER NAME =" at -228.5,-858.49 h60
  text "PLOT NAME =" at -228.5,-1064.34 h60
  text ".plot_File_Name" at 577,-1064.34 h60
  text "GENERATED    :" at 2250,-1064.34 h60
  text ".Print_Date" at 3119.5,-1064.34 h60
  text ".Print_Time" at 3848.5,-1064.34 h60
  text "TEXAS INSTRUMENTS" at 5113,-1064.34 h60
M12 Stackup:
  drawing of 815 lines, arcs and shapes, not listed
  text "Layer" at 14605.06,13091.48 h60
  text "Name" at 15014.97,13091.48 h60
  text "Material" at 15944.72,13091.48 h60
  text "Thickness" at 16804.48,13091.48 h60
  text "Constant" at 17454.32,13091.48 h60
  text "Board Layer Stack" at 18024.18,13091.48 h60
  text "Top Overlay" at 15014.97,12971.48 h60
  text "Top Solder" at 15014.97,12851.48 h60
  text "Solder Resist" at 15944.72,12851.48 h60
  text "0.40mil" at 16804.48,12851.48 h60
  text "3.5" at 17454.32,12851.48 h60
  text "1" at 14605.06,12731.48 h60
  text "Top Layer" at 15014.97,12731.48 h60
  text "2.40mil" at 16804.48,12731.48 h60
  text "Dielectric 1" at 15014.97,12611.48 h60
  text "FR-4 High Tg" at 15944.72,12611.48 h60
  text "8.00mil" at 16804.48,12611.48 h60
  text "3.9" at 17454.32,12611.48 h60
  text "2" at 14605.06,12491.48 h60
  text "Layer 1" at 15014.97,12491.48 h60
  text "CF-004" at 15944.72,12491.48 h60
  text "3.60mil" at 16804.48,12491.48 h60
  text "Dielectric 2" at 15014.97,12371.48 h60
  text "FR-4 High Tg" at 15944.72,12371.48 h60
  text "6.00mil" at 16804.48,12371.48 h60
  text "3.9" at 17454.32,12371.48 h60
  text "3" at 14605.06,12251.48 h60
  text "Layer 2" at 15014.97,12251.48 h60
  text "CF-004" at 15944.72,12251.48 h60
  text "3.60mil" at 16804.48,12251.48 h60
  text "Dielectric 3" at 15014.97,12131.48 h60
  text "FR-4 High Tg" at 15944.72,12131.48 h60
  text "6.00mil" at 16804.48,12131.48 h60
  text "3.9" at 17454.32,12131.48 h60
  text "4" at 14605.06,12011.48 h60
  text "Layer 3" at 15014.97,12011.48 h60
  text "CF-004" at 15944.72,12011.48 h60
  text "3.60mil" at 16804.48,12011.48 h60
  text "Dielectric 4" at 15014.97,11891.48 h60
  text "FR-4 High Tg" at 15944.72,11891.48 h60
  text "6.00mil" at 16804.48,11891.48 h60
  text "3.9" at 17454.32,11891.48 h60
  text "5" at 14605.06,11771.48 h60
  text "Layer 4" at 15014.97,11771.48 h60
  text "CF-004" at 15944.72,11771.48 h60
  text "3.60mil" at 16804.48,11771.48 h60
  text "Dielectric 5" at 15014.97,11651.48 h60
  text "FR-4 High Tg" at 15944.72,11651.48 h60
  text "6.00mil" at 16804.48,11651.48 h60
  text "3.9" at 17454.32,11651.48 h60
  text "6" at 14605.06,11531.48 h60
  text "Layer 5" at 15014.97,11531.48 h60
  text "CF-004" at 15944.72,11531.48 h60
  text "3.60mil" at 16804.48,11531.48 h60
  text "Dielectric 6" at 15014.97,11411.48 h60
  text "FR-4 High Tg" at 15944.72,11411.48 h60
  text "6.00mil" at 16804.48,11411.48 h60
  text "3.9" at 17454.32,11411.48 h60
  text "7" at 14605.06,11291.48 h60
  text "Layer 6" at 15014.97,11291.48 h60
  text "CF-004" at 15944.72,11291.48 h60
  text "3.60mil" at 16804.48,11291.48 h60
  text "Dielectric 7" at 15014.97,11171.48 h60
  text "FR-4 High Tg" at 15944.72,11171.48 h60
  text "6.00mil" at 16804.48,11171.48 h60
  text "3.9" at 17454.32,11171.48 h60
  text "8" at 14605.06,11051.48 h60
  text "Layer 7" at 15014.97,11051.48 h60
  text "CF-004" at 15944.72,11051.48 h60
  text "3.60mil" at 16804.48,11051.48 h60
  text "Dielectric 8" at 15014.97,10931.48 h60
  text "FR-4 High Tg" at 15944.72,10931.48 h60
  text "6.00mil" at 16804.48,10931.48 h60
  text "3.9" at 17454.32,10931.48 h60
  text "9" at 14605.06,10811.48 h60
  text "Layer 8" at 15014.97,10811.48 h60
  text "CF-004" at 15944.72,10811.48 h60
  text "3.60mil" at 16804.48,10811.48 h60
  text "Dielectric 9" at 15014.97,10691.48 h60
  text "FR-4 High Tg" at 15944.72,10691.48 h60
  text "6.00mil" at 16804.48,10691.48 h60
  text "3.9" at 17454.32,10691.48 h60
  text "10" at 14605.06,10571.48 h60
  text "Layer 9" at 15014.97,10571.48 h60
  text "CF-004" at 15944.72,10571.48 h60
  text "3.60mil" at 16804.48,10571.48 h60
  text "Dielectric 10" at 15014.97,10451.48 h60
  text "FR-4 High Tg" at 15944.72,10451.48 h60
  text "6.00mil" at 16804.48,10451.48 h60
  text "3.9" at 17454.32,10451.48 h60
  text "11" at 14605.06,10331.48 h60
  text "Layer 10" at 15014.97,10331.48 h60
  text "CF-004" at 15944.72,10331.48 h60
  text "3.60mil" at 16804.48,10331.48 h60
  text "Dielectric 11" at 15014.97,10211.48 h60
  text "FR-4 High Tg" at 15944.72,10211.48 h60
  text "6.00mil" at 16804.48,10211.48 h60
  text "3.9" at 17454.32,10211.48 h60
  text "12" at 14605.06,10091.48 h60
  text "Layer 11" at 15014.97,10091.48 h60
  text "CF-004" at 15944.72,10091.48 h60
  text "3.60mil" at 16804.48,10091.48 h60
  text "Dielectric 12" at 15014.97,9971.48 h60
  text "FR-4 High Tg" at 15944.72,9971.48 h60
  text "6.00mil" at 16804.48,9971.48 h60
  text "3.9" at 17454.32,9971.48 h60
  text "13" at 14605.06,9851.48 h60
  text "Layer 12" at 15014.97,9851.48 h60
  text "CF-004" at 15944.72,9851.48 h60
  text "3.60mil" at 16804.48,9851.48 h60
  text "Dielectric 13" at 15014.97,9731.48 h60
  text "FR-4 High Tg" at 15944.72,9731.48 h60
  text "8.00mil" at 16804.48,9731.48 h60
  text "3.9" at 17454.32,9731.48 h60
  text "14" at 14605.06,9611.48 h60
  text "Bottom Layer" at 15014.97,9611.48 h60
  text "2.40mil" at 16804.48,9611.48 h60
  text "Bottom Solder" at 15014.97,9491.48 h60
  text "Solder Resist" at 15944.72,9491.48 h60
  text "0.40mil" at 16804.48,9491.48 h60
  text "3.5" at 17454.32,9491.48 h60
  text "Bottom Overlay" at 15014.97,9371.48 h60
  text ".Layer_Name" at 577,-858.49 h60
M13 Component Bodies Top:
  text ".Layer_Name" at 577,-858.49 h60
M14 Component Bodies Bottom:
  text ".Layer_Name" at 577,-858.49 h60
M15 Courtyards Top:
  text ".Layer_Name" at 577,-858.49 h60
M16 Courtyards Bottom:
  text ".Layer_Name" at 577,-858.49 h60
Drill Drawing:
  circle w10: c203.98,4722.56 r27.63
  lines w10: 176.36,4819.25 203.98,4833.06 231.61,4819.25 217.8,4846.88 231.61,4874.5 203.98,4860.69 176.36,4874.5 190.17,4846.88 176.36,4819.25 ; 176.36,4957.38 190.17,4957.38 190.17,4943.57 217.8,4943.57 217.8,4957.38 231.61,4957.38 231.61,4985.01 217.8,4985.01 217.8,4998.82 190.17,4998.82 190.17,4985.01 176.36,4985.01 176.36,4957.38 ; 176.36,5123.14 231.61,5123.14 203.98,5067.89 176.36,5123.14 ; 176.36,5192.21 231.61,5192.21 231.61,5247.46 176.36,5247.46 176.36,5192.21 ; 176.36,5330.34 190.17,5330.34 203.98,5316.53 217.8,5330.34 231.61,5330.34 217.8,5344.16 231.61,5357.97 217.8,5357.97 203.98,5371.78 190.17,5357.97 176.36,5357.97 190.17,5344.16 176.36,5330.34
  lines w12: 126.27,4657.63 3357.75,4657.63 ; 126.27,5403.55 3357.75,5403.55 ; 464.13,4533.31 464.13,5527.87 ; 796.13,4533.31 796.13,5527.87 ; 1432.69,4533.31 1432.69,5527.87 ; 1691.83,4533.31 1691.83,5527.87 ; 2066.99,4533.31 2066.99,5527.87 ; 2791.32,4533.31 2791.32,5527.87 ; 126.27,4533.31 3357.75,4533.31 3357.75,5527.87 126.27,5527.87 126.27,4533.31
  text "Symbol" at 200.86,5440.85 h72
  text "Quantity" at 501.42,5440.85 h72
  text "Finished Hole Size" at 833.43,5440.85 h72
  text "Plated" at 1469.99,5440.85 h72
  text "Hole Type" at 1729.13,5440.85 h72
  text "Drill Layer Pair" at 2104.29,5440.85 h72
  text "Hole Tolerance" at 2828.62,5440.85 h72
  text "2" at 501.42,5316.53 h60
  text "114.17mil (2.900mm)" at 833.43,5316.53 h60
  text "NPTH" at 1469.99,5316.53 h60
  text "Round" at 1729.13,5316.53 h60
  text "Top Layer - Bottom Layer" at 2104.29,5316.53 h60
  text "60" at 501.42,5192.21 h60
  text "7.87mil (0.200mm)" at 833.43,5192.21 h60
  text "PTH" at 1469.99,5192.21 h60
  text "Round" at 1729.13,5192.21 h60
  text "Top Layer - Bottom Layer" at 2104.29,5192.21 h60
  text "108" at 501.42,5067.89 h60
  text "10.00mil (0.254mm)" at 833.43,5067.89 h60
  text "PTH" at 1469.99,5067.89 h60
  text "Round" at 1729.13,5067.89 h60
  text "Top Layer - Bottom Layer" at 2104.29,5067.89 h60
  text "153" at 501.42,4943.57 h60
  text "12.00mil (0.305mm)" at 833.43,4943.57 h60
  text "PTH" at 1469.99,4943.57 h60
  text "Round" at 1729.13,4943.57 h60
  text "Top Layer - Bottom Layer" at 2104.29,4943.57 h60
  text "8" at 501.42,4819.25 h60
  text "27.95mil (0.710mm)" at 833.43,4819.25 h60
  text "PTH" at 1469.99,4819.25 h60
  text "Round" at 1729.13,4819.25 h60
  text "Top Layer - Bottom Layer" at 2104.29,4819.25 h60
  text "13" at 501.42,4694.93 h60
  text "64.96mil (1.650mm)" at 833.43,4694.93 h60
  text "PTH" at 1469.99,4694.93 h60
  text "Round" at 1729.13,4694.93 h60
  text "Top Layer - Bottom Layer" at 2104.29,4694.93 h60
  text "344 Total" at 501.42,4570.61 h60
  text ".Layer_Name" at 577,-858.49 h60
M17 Embedded Cavity:
  text ".Layer_Name" at 577,-858.49 h60
M18 Embedded Assembly:
  text ".Layer_Name" at 577,-858.49 h60
M19 Embedded Keepout:
  text ".Layer_Name" at 567,-858.49 h60

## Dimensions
0,0 to 0,255.91 on M2 Board Dimensions
2750.2,-173.02 to 3750.2,-173.02 on M2 Board Dimensions
0,0 to 2299.21,0 on M2 Board Dimensions
0,255.91 to 0,1157.48 on M2 Board Dimensions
